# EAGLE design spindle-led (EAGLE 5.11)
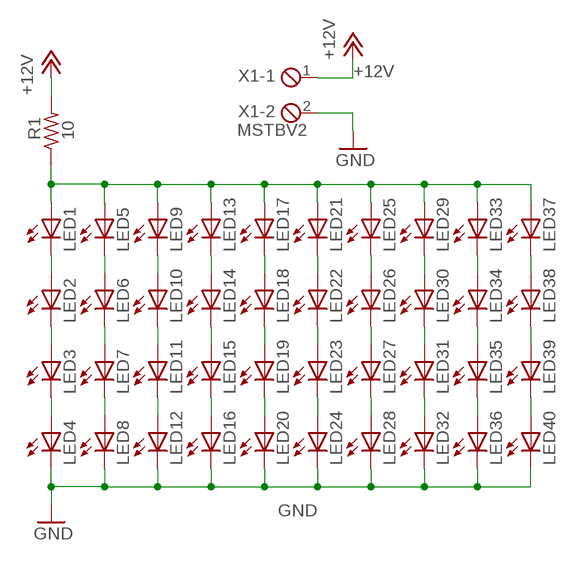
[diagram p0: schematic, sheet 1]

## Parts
LED1  LED5MM  [LED5MM]
LED2  LED5MM  [LED5MM]
LED3  LED5MM  [LED5MM]
LED4  LED5MM  [LED5MM]
LED5  LED5MM  [LED5MM]
LED6  LED5MM  [LED5MM]
LED7  LED5MM  [LED5MM]
LED8  LED5MM  [LED5MM]
LED9  LED5MM  [LED5MM]
LED10  LED5MM  [LED5MM]
LED11  LED5MM  [LED5MM]
LED12  LED5MM  [LED5MM]
LED13  LED5MM  [LED5MM]
LED14  LED5MM  [LED5MM]
LED15  LED5MM  [LED5MM]
LED16  LED5MM  [LED5MM]
LED17  LED5MM  [LED5MM]
LED18  LED5MM  [LED5MM]
LED19  LED5MM  [LED5MM]
LED20  LED5MM  [LED5MM]
LED21  LED5MM  [LED5MM]
LED22  LED5MM  [LED5MM]
LED23  LED5MM  [LED5MM]
LED24  LED5MM  [LED5MM]
LED25  LED5MM  [LED5MM]
LED26  LED5MM  [LED5MM]
LED27  LED5MM  [LED5MM]
LED28  LED5MM  [LED5MM]
LED29  LED5MM  [LED5MM]
LED30  LED5MM  [LED5MM]
LED31  LED5MM  [LED5MM]
LED32  LED5MM  [LED5MM]
LED33  LED5MM  [LED5MM]
LED34  LED5MM  [LED5MM]
LED35  LED5MM  [LED5MM]
LED36  LED5MM  [LED5MM]
LED37  LED5MM  [LED5MM]
LED38  LED5MM  [LED5MM]
LED39  LED5MM  [LED5MM]
LED40  LED5MM  [LED5MM]
R1  10  R-US_0207/10  [0207/10]
X1  MSTBV2  MPT2  [2POL254]

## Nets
+12V: R1.2 X1.1
GND: LED4.K(C) LED8.K(C) LED12.K(C) LED16.K(C) LED20.K(C) LED24.K(C) LED28.K(C) LED32.K(C) LED36.K(C) LED40.K(C) X1.2
N$1: LED1.K(C) LED2.A
N$2: LED2.K(C) LED3.A
N$3: LED3.K(C) LED4.A
N$4: LED5.K(C) LED6.A
N$5: LED6.K(C) LED7.A
N$6: LED7.K(C) LED8.A
N$7: LED9.K(C) LED10.A
N$8: LED10.K(C) LED11.A
N$9: LED11.K(C) LED12.A
N$10: LED13.K(C) LED14.A
N$11: LED14.K(C) LED15.A
N$12: LED15.K(C) LED16.A
N$13: LED17.K(C) LED18.A
N$14: LED18.K(C) LED19.A
N$15: LED19.K(C) LED20.A
N$16: LED21.K(C) LED22.A
N$17: LED22.K(C) LED23.A
N$18: LED23.K(C) LED24.A
N$19: LED25.K(C) LED26.A
N$20: LED26.K(C) LED27.A
N$21: LED27.K(C) LED28.A
N$22: LED29.K(C) LED30.A
N$23: LED30.K(C) LED31.A
N$24: LED31.K(C) LED32.A
N$25: LED33.K(C) LED34.A
N$26: LED34.K(C) LED35.A
N$27: LED35.K(C) LED36.A
N$28: LED37.K(C) LED38.A
N$29: LED38.K(C) LED39.A
N$30: LED39.K(C) LED40.A
N$32: LED1.A LED5.A LED9.A LED13.A LED17.A LED21.A LED25.A LED29.A LED33.A LED37.A R1.1

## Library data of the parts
LED1-LED40 = adafruit:LED: LED
R1 = adafruit:R-US_: RESISTOR, American symbol
X1 = con-phoenix-254:MPT2: PHOENIX CONNECTOR; OC_FARNELL: unknown; OC_NEWARK: unknown

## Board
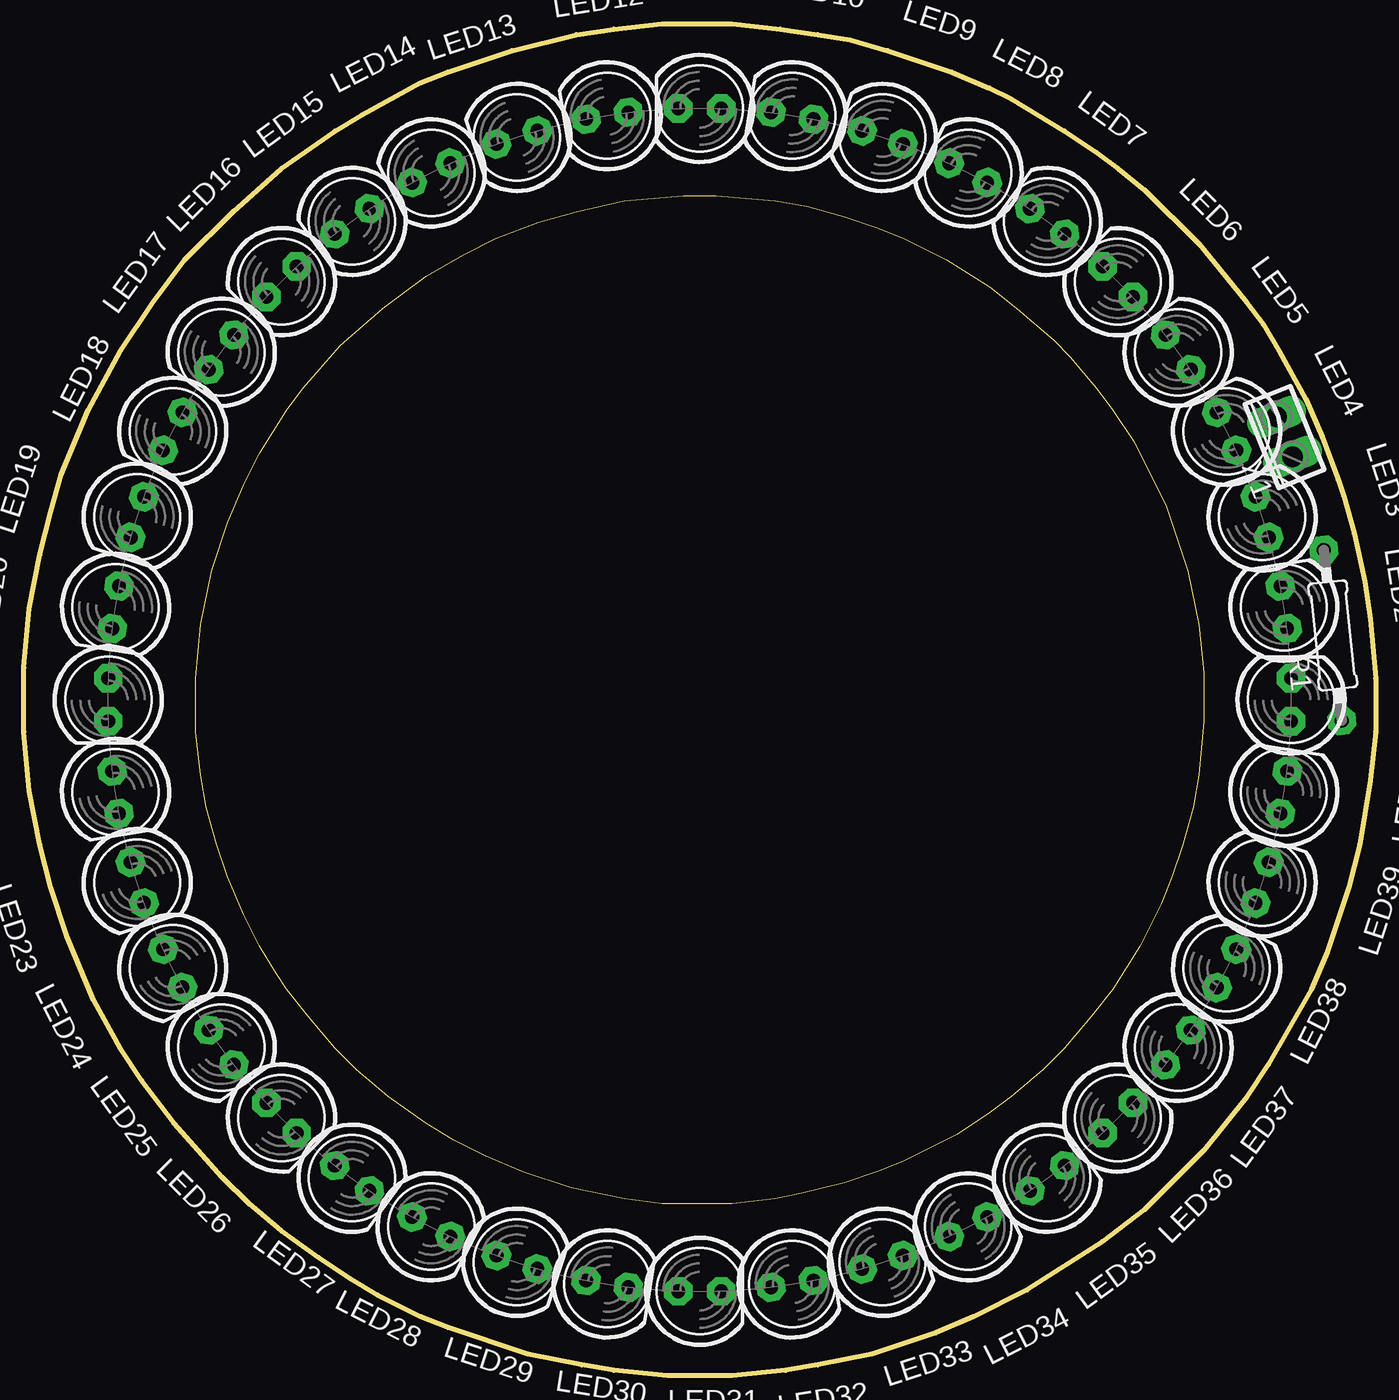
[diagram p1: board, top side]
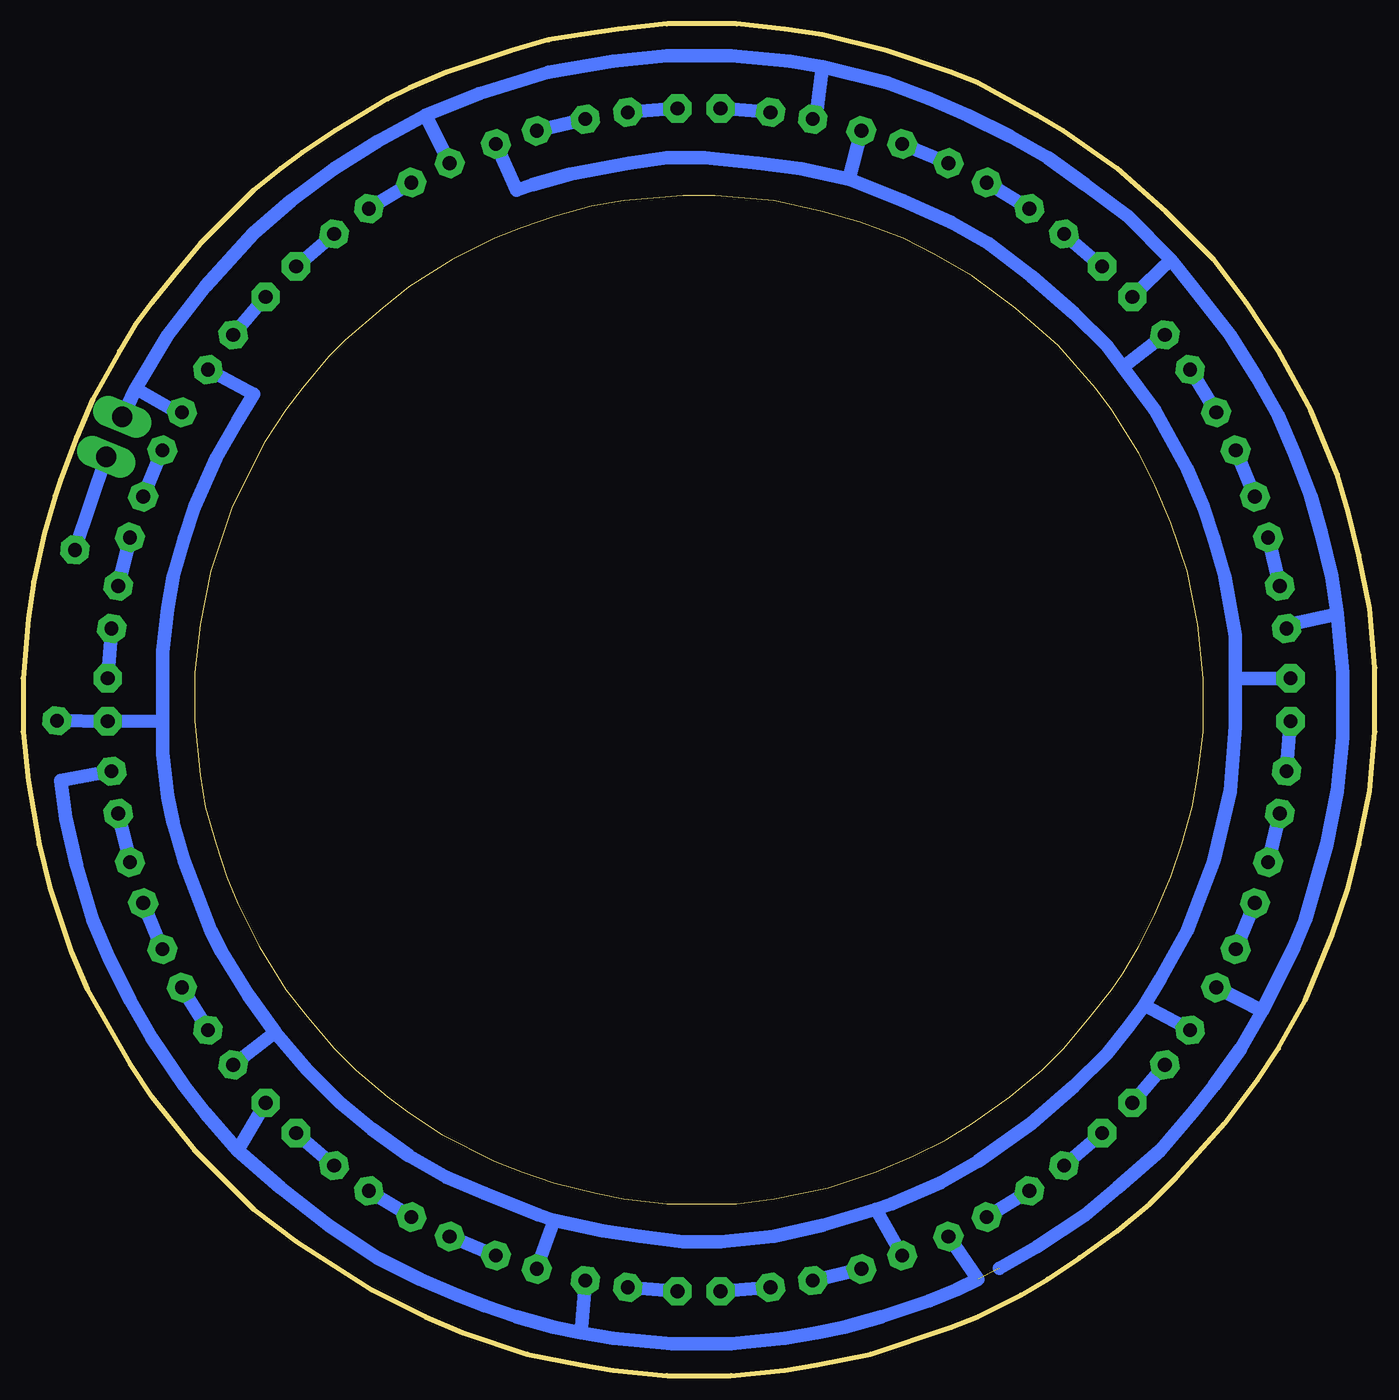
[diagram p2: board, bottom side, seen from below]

No outline drawn. Coordinates in mm, seen from the top.
Copper layers (1*16): Top 0.035mm / dielectric 1.5mm / Bottom 0.035mm
Design rules "default": minimum track width 10mil, minimum drill 24mil, track to track 8mil, track to pad 8mil, pad to pad 8mil, via to via 8mil, smd to smd 8mil, copper to edge 40mil, drill to drill 8mil, minimum pad ring 10mil, minimum via ring 8mil, stop-mask expansion 4mil, vias tented up to drill 0mil, thermal gap 10mil
Milling: 158 lines

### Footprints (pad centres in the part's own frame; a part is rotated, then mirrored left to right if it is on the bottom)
LED5MM = drill 0.813 pad 1.676 octagon: A -1.27,0; K 1.27,0
0207/10 = drill 0.813 pad 1.676 octagon: 1 -5.08,0; 2 5.08,0
2POL254 = drill 1.2 long: 1 -1.27,0; 2 1.27,0

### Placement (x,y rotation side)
LED1  75,40 90 top
LED2  74.57,45.48 99 top
LED3  73.29,50.82 108 top
LED4  71.19,55.89 117 top
LED5  68.32,60.57 126 top
LED6  64.75,64.75 135 top
LED7  60.57,68.32 144 top
LED8  55.89,71.19 153 top
LED9  50.82,73.29 162 top
LED10  45.48,74.57 171 top
LED11  40,75 180 top
LED12  34.52,74.57 189 top
LED13  29.18,73.29 198 top
LED14  24.11,71.19 207 top
LED15  19.43,68.32 216 top
LED16  15.25,64.75 225 top
LED17  11.68,60.57 234 top
LED18  8.81,55.89 243 top
LED19  6.71,50.82 252 top
LED20  5.43,45.48 261 top
LED21  5,40 270 top
LED22  5.43,34.52 279 top
LED23  6.71,29.18 288 top
LED24  8.81,24.11 297 top
LED25  11.68,19.43 306 top
LED26  15.25,15.25 315 top
LED27  19.43,11.68 324 top
LED28  24.11,8.81 333 top
LED29  29.18,6.71 342 top
LED30  34.52,5.43 351 top
LED31  40,5 0 top
LED32  45.48,5.43 9 top
LED33  50.82,6.71 18 top
LED34  55.89,8.81 27 top
LED35  60.57,11.68 36 top
LED36  64.75,15.25 45 top
LED37  68.32,19.43 54 top
LED38  71.19,24.11 63 top
LED39  73.29,29.18 72 top
LED40  74.57,34.52 81 top
R1  77.47,43.81 96 top
X1  74.61,55.56 112 top

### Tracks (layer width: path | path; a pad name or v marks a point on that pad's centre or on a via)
+12V
  Bottom 0.813: R1.2 X1.1
GND  (1 unrouted)
  Bottom 0.813: LED40.K 77.79,35.24 77.47,33.02 76.83,30.16 75.88,26.99 74.93,24.77 73.66,22.23 72.39,20 70.48,17.14 69.22,15.56 67.31,13.34 | 67.31,13.34 LED36.K | 67.31,13.34 64.77,11.11 61.91,8.89 59.05,6.99 56.52,5.71 54.29,4.76 52.7,4.13 50.8,3.49 48.58,2.86 46.99,2.54 | 46.99,2.54 LED32.K | 46.99,2.54 45.09,2.22 41.59,1.91 38.1,1.91 34.92,2.22 33.02,2.54 31.43,2.86 29.21,3.49 26.35,4.45 24.77,5.08 23.5,5.71 LED28.K | 6.67,21.59 LED24.K | 6.67,21.59 7.94,19.37 9.53,17.14 10.79,15.56 12.7,13.34 15.24,11.11 17.14,9.53 20,7.62 22.23,6.35 | LED20.K 5.08,44.45 2.22,45.09 | 2.22,45.09 1.91,41.59 1.91,37.78 2.22,34.61 2.86,31.43 4.13,26.99 4.76,25.4 6.67,21.59 | 12.06,66.04 LED16.K | 12.06,66.04 10.79,64.45 8.57,61.59 6.99,59.05 5.71,56.83 4.76,54.61 3.81,52.07 3.17,49.85 2.54,47.31 2.22,45.09 | LED12.K 33.02,74.93 32.7,77.47 | 32.7,77.47 28.89,76.52 26.35,75.56 24.13,74.61 21.59,73.34 19.37,72.07 17.14,70.48 14.61,68.58 12.06,66.04 | 56.2,74.61 LED8.K | 56.2,74.61 53.02,75.88 48.9,77.15 45.09,77.79 41.91,78.11 38.1,78.11 34.61,77.79 32.7,77.47 | LED4.K 71.12,57.15 73.34,58.42 | 73.34,58.42 71.44,61.59 69.22,64.45 66.36,67.63 64.14,69.53 61.59,71.44 59.05,73.03 56.2,74.61 | 73.34,58.42 X1.2
N$1
  Bottom 0.813: LED1.K LED2.A
N$2
  Bottom 0.813: LED2.K LED3.A
N$3
  Bottom 0.813: LED3.K LED4.A
N$4
  Bottom 0.813: LED6.A LED5.K
N$5
  Bottom 0.813: LED7.A LED6.K
N$6
  Bottom 0.813: LED8.A LED7.K
N$7
  Bottom 0.813: LED10.A LED9.K
N$8
  Bottom 0.813: LED11.A LED10.K
N$9
  Bottom 0.813: LED12.A LED11.K
N$10
  Bottom 0.813: LED14.A LED13.K
N$11
  Bottom 0.813: LED15.A LED14.K
N$12
  Bottom 0.813: LED16.A LED15.K
N$13
  Bottom 0.813: LED18.A LED17.K
N$14
  Bottom 0.813: LED19.A LED18.K
N$15
  Bottom 0.813: LED20.A LED19.K
N$16
  Bottom 0.813: LED22.A LED21.K
N$17
  Bottom 0.813: LED23.A LED22.K
N$18
  Bottom 0.813: LED24.A LED23.K
N$19
  Bottom 0.813: LED26.A LED25.K
N$20
  Bottom 0.813: LED27.A LED26.K
N$21
  Bottom 0.813: LED28.A LED27.K
N$22
  Bottom 0.813: LED29.K LED30.A
N$23
  Bottom 0.813: LED31.A LED30.K
N$24
  Bottom 0.813: LED31.K LED32.A
N$25
  Bottom 0.813: LED33.K LED34.A
N$26
  Bottom 0.813: LED34.K LED35.A
N$27
  Bottom 0.813: LED35.K LED36.A
N$28
  Bottom 0.813: LED37.K LED38.A
N$29
  Bottom 0.813: LED38.K LED39.A
N$30
  Bottom 0.813: LED39.K LED40.A
N$32
  Bottom 0.813: LED5.A 66.36,58.1 67.31,56.52 68.58,54.29 69.85,51.44 70.48,49.53 71.12,47.31 71.44,45.4 71.75,42.86 71.75,38.73 | 71.75,38.73 LED1.A R1.1 | 71.75,38.73 71.75,36.83 71.44,34.29 71.12,32.7 70.48,30.48 68.9,26.35 68.26,25.08 66.67,22.54 65.09,20.32 | 65.09,20.32 LED37.A | 65.09,20.32 63.18,18.1 61.28,16.19 59.37,14.61 57.15,13.02 54.93,11.75 52.7,10.79 49.53,9.53 48.58,9.21 | 48.58,9.21 LED33.A | 48.58,9.21 45.72,8.57 43.5,8.26 40.96,7.94 38.73,7.94 35.56,8.26 32.7,8.89 29.53,9.84 | 29.53,9.84 LED29.A | LED25.A 13.65,21.91 | 13.65,21.91 14.61,20.64 15.88,19.05 17.78,17.14 20.32,14.92 23.5,12.7 25.72,11.43 28.57,10.16 29.53,9.84 | 8.26,41.27 LED21.A | 8.26,41.27 8.26,38.42 8.57,34.61 9.53,30.48 11.11,26.35 12.7,23.5 13.65,21.91 | 14.92,59.69 LED17.A | 14.92,59.69 13.02,57.15 11.11,53.66 10.16,51.44 9.53,49.53 8.89,47.31 8.26,43.81 8.26,41.27 | 31.11,70.8 LED13.A | 31.11,70.8 27.94,69.53 25.08,68.26 22.86,66.99 20.32,65.09 17.78,62.87 15.88,60.96 14.92,59.69 | 31.11,70.8 33.97,71.44 36.51,71.75 39.69,72.07 41.91,72.07 44.13,71.75 47.62,71.12 49.85,70.48 50.8,70.17 LED9.A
